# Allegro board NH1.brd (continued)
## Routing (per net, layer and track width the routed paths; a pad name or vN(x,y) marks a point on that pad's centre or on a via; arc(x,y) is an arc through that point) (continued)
PMU_AC_PRESENT: length 3.1
  TOP w0.102: U1.B8 6.15,49.48 5.22,49.48 4.79,49.92 4.13,49.92 R1AS1.2
PMU_BATLOW_N: length 3.6
  TOP w0.102: R1AS2.2 4.46,50.65 4.68,50.42 5.45,50.42 5.7,50.17 6.79,50.17 U1.C9
PMU_PWRBTN_N: length 54.4
  TOP w0.102: v1(2.35,41.69) 2.5,41.53 4.53,41.53 4.72,41.35 4.72,40.24 4.84,40.12 5.44,40.12 5.45,40.14 5.69,40.14 5.73,40.1 6.65,40.1 7.07,39.68 7.07,39.43 7.21,39.3 9.93,39.3 9.97,39.34 10.78,39.34 10.91,39.46 10.91,40.9 11.19,41.18 12.35,41.18 12.41,41.23 12.52,41.23 12.88,41.59 12.88,42.47 13.63,43.21 16.42,43.21 17.22,42.41 17.22,39.72 17.65,39.3 18.41,39.3 18.59,39.12 20.19,39.12 20.41,38.9 20.41,37.86 20.74,37.53 24.22,37.53 24.46,37.78 24.75,37.78 25.79,38.82 28.03,38.82 v1(28.41,39.2) ; v1(5.32,50.98) 5.52,50.81 U1.A10
  IN1 w0.102: v1(5.32,50.98) 5.14,50.81 2.47,50.81 1.76,50.09 1.76,42.27 v1(2.35,41.69)
  BOTTOM w0.102: v1(28.41,39.2) 29.06,39.85 R1P1.1 27.54,40.37 27.11,40.8 CR1P2.3
PMU_SLP_S0IX_N: length 33.6
  TOP w0.102: U1.C7 7.02,48.5 7.02,48.51 6.65,48.51 6.59,48.44 6.04,48.44 5.73,48.13 5.71,48.13 5.55,47.97 5.55,47.51 v1(5.42,47.38) ; TP29.1 10.37,39.1 7.12,39.1 6.87,39.35 6.87,39.6 6.57,39.9 5.66,39.9 v1(5.55,39.78) ; U1AP1.56 17.56,33.33 v1(16.93,32.69)
  IN1 w0.102: v1(5.55,39.78) 5.6,39.78 6.41,40.6 6.41,45.88 5.75,46.54 5.75,47.05 v1(5.42,47.38)
  IN2 w0.102: v1(5.55,39.78) 5.55,39.78 5.55,38.54 7.81,36.28 8.06,36.28 9.43,34.9 15.4,34.9 16.93,33.38 v1(16.93,32.69)
PMU_SLP_S3_N: length 117.6
  TOP w0.102: U1.C8 6.88,49.16 6.6,48.88 6.19,48.88 5.68,48.37 4.84,48.37 v1(4.51,48.04)
  IN2 w0.102: v1(4.51,48.04) 4.51,48.95 3.85,49.61 3.85,55.73 3.36,56.22 3.36,57.84 4.47,58.95 4.47,61.93 4.48,61.95 4.48,61.96 4.48,66.69 2.93,68.23 2.93,73.39 2.58,73.74 2.58,74.05 2.89,74.36 3.13,74.36 3.69,74.92 3.69,78.52 3.96,78.78 4.29,78.78 5.27,79.76 5.27,83.07 7.12,84.92 8.67,84.92 11.2,87.44 12.39,87.44 v1(12.79,87.84)
  BOTTOM w0.102: v1(12.79,87.84) 12.96,87.66 13.99,87.66 14.01,87.69 14.31,87.69 14.33,87.66 15.4,87.66 15.41,87.65 15.51,87.65 16.1,87.06 21.04,87.06 21.51,87.53 24.93,87.53 25.49,88.09 25.78,88.09 26.17,88.47 30.56,88.47 32.17,86.86 32.17,85.32 31.61,84.76 31.61,84.34 30.74,83.48 30.74,82.72 30.08,82.06 30.08,80.48 29.47,79.87 29.47,74.71 29.27,74.5 29.27,73.39 29.5,73.16 29.78,73.16 30.06,72.88 30.06,72.36 29.68,71.98 29.68,71.97 29.67,71.96 29.67,67.97 29.7,67.94 29.93,67.71 30.15,67.5 30.15,64.6 29.63,64.08 29.63,61.31 31.15,59.79 31.15,59.26 31.15,52.2 29.22,50.27 27.59,50.27 27.04,49.71 Q1HDMI3.2
PWRON: length 31
  TOP w0.102: U1AP1.62 v1(15.75,33.74)
  IN1 w0.102: v2(28.71,37.22) 27.09,38.84 26.38,38.84 26.22,38.99 21.45,38.99 19.92,37.47 16.16,37.47 15.56,36.86 15.56,33.94 v1(15.75,33.74)
  IN2 w0.102: v2(28.71,37.22) 29.22,37.72 29.22,40.14 27.85,41.51 v1(27.85,43.52)
  BOTTOM w0.203: v1(27.85,43.52) 28.43,42.93 CR1P2.2 29.24,42.93 C1P3.1 30.74,44.44 30.74,45.39 R1P2.2
REXT_ALS: length 2.2
  TOP w0.102: v1(25.82,90.53) 26.41,89.93 EU1HDMI1.16
  BOTTOM w0.102: R1HDMI2.2 26.21,90.14 v1(25.82,90.53)
RSMRST_N: length 17.4
  TOP w0.102: U1AP1.75 10.55,35.29 v1(10.2,35.64) ; U1.F3 9.12,45.82 v1(9.41,45.53)
  IN1 w0.102: v1(9.41,45.53) 9.14,45.27 9.14,44.34 9.34,44.15 9.74,43.74 10.33,43.74 10.7,43.37 10.7,38.87 10.27,38.44 10.27,35.72 v1(10.2,35.64)
  BOTTOM w0.102: R1AP3.1 9.78,31.59 10.02,31.83 10.02,33.41 9.99,33.44 9.99,35.44 v1(10.2,35.64)
RTEST_N: length 7
  TOP w0.102: C1AS5.1 R1AS5.2 4.43,43.61 4.43,43.75 5.56,44.88 5.97,44.88 5.98,44.89 5.98,44.89 6.16,45.06 6.16,45.35 6.38,45.57 8.17,45.57 U1.E3
RTL8723BS_EN: length 47
  TOP w0.102: R1WF10.1 3.87,19.86 3.87,17.14 4.07,16.94 4.07,16.14 4.63,15.58 v1(4.63,15.58) ; U1.C5 7.43,47.47 v1(7.43,48.82)
  IN1 w0.102: v1(4.63,15.58) 4.98,15.92 4.98,17.14 6.11,18.27 6.11,23.52 5.14,24.49 5.14,24.61 5.14,25.94 5.5,26.3 5.5,27.82 7.2,29.52 7.2,32.8 7.78,33.39 7.78,34.39 6.64,35.53 6.64,36.63 5.03,38.24 5.03,41.2 3.69,42.54 3.69,47.69 4.37,48.37 4.9,48.37 5.05,48.21 5.89,48.21 6.49,48.82 v1(7.43,48.82)
RTL8723BS_EN_R: length 15.6
  TOP w0.102: R65.1 3.23,21.28 R1WF10.2 3.12,20.49 2.88,20.49 R1WF1.2 2.89,19.83 3.2,19.83 3.67,19.36 3.67,17.35 3.31,16.99 3.31,16.39 3.62,16.08 v1(3.72,16.08)
  IN1 w0.102: v2(4.18,10.22) 4.18,15.02 3.72,15.48 v1(3.72,16.08)
  BOTTOM w0.102: U1WF1.13 3.43,9.44 4.18,10.19 v2(4.18,10.22)
SDMMC1_RCOMP: length 3.7
  TOP w0.254: R1AS43.1 23.89,46.77 22.81,47.85 U1.AE6
SDMMC2_CLK: length 46.9
  TOP w0.102: v1(22,50.18) 22,50.15 U1.AE9
  IN2 w0.102: v1(13.21,19.28) 13.22,19.28 13.42,19.49 13.42,20.91 13.4,20.93 13.83,21.37 15.96,21.37 16.42,21.82 16.82,21.82 17.97,22.97 19.16,22.97 19.33,23.14 23.25,23.14 24.24,24.14 24.24,31.8 23.88,32.16 23.88,34.85 23.07,35.66 23.07,49.09 22.65,49.52 22.65,49.52 v1(22,50.18)
  BOTTOM w0.14: C1WF21.2 13.55,23.06 13.62,22.99 U1WF1.33 13.62,20.71 13.21,20.3 v1(13.21,19.28)
SDMMC2_CMD: length 48
  TOP w0.102: U1.AC9 v1(20.71,49.48)
  IN2 w0.102: v1(20.71,49.48) 21.04,49.81 21.48,49.81 21.49,49.8 21.51,49.8 22.72,48.6 22.72,35.51 23.53,34.7 23.53,32.01 23.89,31.65 23.89,24.29 23.1,23.5 19.19,23.5 19.01,23.32 17.82,23.32 16.68,22.18 16.27,22.18 15.81,21.72 13.68,21.72 12.96,21.01 12.96,20.02 12.61,19.66 8.47,19.66 v1(7.96,20.17)
  BOTTOM w0.14: v1(7.96,20.17) 8.37,20.58 U1WF1.28
SDMMC2_D_0: length 52.9
  TOP w0.102: U1.AB11 19.4,50.83 v1(19.4,50.83)
  IN2 w0.102: v1(19.4,50.83) 19.95,51.38 22.63,51.38 24.52,49.49 24.52,36.01 25.15,35.37 25.15,32.69 25.51,32.33 25.51,23.61 23.09,21.19 21.11,21.19 20.6,21.7 18.52,21.7 14.58,17.76 v1(12.16,17.76)
  BOTTOM w0.14: v1(12.16,17.76) 12.16,20.45 12.57,20.86 U1WF1.32
SDMMC2_D_1: length 52.3
  TOP w0.102: U1.AB10 19.4,50.18 v1(19.4,50.18)
  IN2 w0.102: v1(19.4,50.18) 20.35,51.13 22.45,51.13 24.17,49.42 24.17,35.93 24.85,35.25 24.85,32.56 25.21,32.2 25.21,23.74 23.65,22.18 19.77,22.18 19.59,22 18.37,22 17.22,20.86 17.2,20.86 14.63,18.29 14.62,18.29 14.46,18.14 v1(11.11,18.14)
  BOTTOM w0.14: U1WF1.31 11.52,20.3 11.11,19.89 v1(11.11,18.14)
SDMMC2_D_2: length 50.6
  TOP w0.102: U1.AC10 v1(20.7,50.18)
  IN2 w0.102: v1(20.7,50.18) 21.24,50.72 21.25,50.72 21.4,50.88 22.25,50.88 23.84,49.29 23.84,35.83 24.54,35.12 24.54,32.43 24.9,32.07 24.9,23.87 23.52,22.48 19.61,22.48 19.43,22.31 18.24,22.31 17.1,21.16 17.07,21.16 14.51,18.6 14.49,18.6 14.41,18.52 v1(10.06,18.52)
  BOTTOM w0.14: v1(10.06,18.52) 10.06,20.15 10.47,20.55 U1WF1.30
SDMMC2_D_3: length 49.4
  TOP w0.102: U1.AD10 v1(21.35,50.18)
  IN2 w0.102: v1(21.35,50.18) 21.35,50.22 21.68,50.55 22.12,50.55 23.43,49.24 23.43,35.8 24.24,34.99 24.24,32.31 24.6,31.95 24.6,23.99 23.39,22.79 19.48,22.79 19.3,22.61 18.11,22.61 16.97,21.47 16.94,21.47 14.38,18.9 v1(9.01,18.9)
  BOTTOM w0.14: U1WF1.29 9.42,19.31 v1(9.01,18.9)
SDMMC3_CD_N: length 58.4
  TOP w0.102: v1(18.07,51.47) U1.Y12 ; J1SD1.9 12.65,12.26 v1(12.61,12.3)
  IN2 w0.102: v1(12.61,20.17) 12.58,20.2 12.58,21.14 13.65,22.2 15.71,22.2 v1(16.09,22.59) 16.09,22.61 17.11,23.63 18.88,23.63 19.06,23.8 22.97,23.8 23.58,24.41 23.58,31.53 23.22,31.88 23.22,34.57 22.36,35.43 22.36,39.86 21.8,40.42 21.8,41.43 21.8,41.43 21.8,46.23 20.19,47.84 18.57,47.84 18.37,48.04 18.37,48.92 18.43,48.98 18.43,50.02 18.07,50.38 v1(18.07,51.47)
  BOTTOM w0.102: v1(18.07,51.47) 18.4,51.8 18.92,51.8 19.16,51.56 19.24,51.56 19.66,51.14 19.76,51.14 R60.2 ; v1(12.61,12.3) 12.71,12.4 12.71,20.07 v1(12.61,20.17)
  BOTTOM w0.254: v1(16.09,22.59) 16.09,22.98 16.95,23.85 C73.1
SDMMC3_CLK: length 52.2
  TOP w0.102: U1.AC12 20.55,51.81 20.86,51.49 22.52,51.49 22.62,51.39 22.77,51.39
  TOP w0.14: v1(25.87,39.4) 26.43,39.96 26.43,41.64 26.8,42.01 26.8,48.48 25.26,50.02 24.74,50.02 23.38,51.39 22.77,51.39 ; U15.6 v1(17.92,12.26)
  IN1 w0.102: v1(22.97,19.92) 21.24,18.24 18.96,18.24 16.57,15.85 16.57,13.36 17.66,12.27 17.91,12.27 v1(17.92,12.26)
  BOTTOM w0.14: v1(25.87,39.4) 25.87,39 27.23,37.63 27.23,33.13 24.42,30.32 24.42,21.9 22.97,20.45 v1(22.97,19.92)
SDMMC3_CLK_CONN: length 8.1
  TOP w0.14: U15.11 15.31,12.26 15.17,12.4 v2(15.02,12.4)
  BOTTOM w0.14: v2(15.02,12.4) 15.02,10.52 15.5,10.04 17.1,10.04 17.46,9.68 17.46,9.07 18.29,8.24 R66.1
SDMMC3_CLK_CONN_R: length 23.5
  TOP w0.14: J1SD1.5 2.25,14.14 2.26,14.15 3.15,14.15 3.21,14.2 4.07,14.2 5.24,13.03 13.02,13.03 v2(13.27,12.78)
  BOTTOM w0.102: v2(13.27,12.78) 14.74,11.31 14.74,9.51 15.4,8.84 16.85,8.84 18.32,7.37 18.32,6.41 18.53,6.21 C418.2 R66.2
SDMMC3_CMD: length 53.8
  TOP w0.102: 22.77,51.03 22.62,51.03 22.41,51.24 20.71,51.24 20.47,51.48 20.05,51.48 U1.AB12
  TOP w0.14: 22.77,51.03 23.26,51.03 24.58,49.72 25.13,49.72 26.5,48.35 26.5,42.14 26.12,41.76 26.12,40.39 v1(25.49,39.76) ; U15.5 v1(18.32,11.86)
  IN1 w0.102: v1(22.41,19.92) 20.99,18.55 18.83,18.55 16.27,15.98 16.27,13.24 17.64,11.87 18.32,11.87 v1(18.32,11.86)
  BOTTOM w0.14: v1(25.49,39.76) 25.49,38.95 26.91,37.52 26.91,33.24 24.11,30.45 24.11,22.03 22.41,20.32 v1(22.41,19.92)
SDMMC3_CMD_CONN: length 14.8
  TOP w0.14: U15.12 14.89,11.86 14.57,11.54 13.64,11.54 13.25,11.92 12.45,11.92 12.44,11.94 J1SD1.3
SDMMC3_D_0: length 52.2
  TOP w0.102: U1.AC11 20.54,50.98 22.23,50.98 22.54,50.68 22.77,50.68
  TOP w0.14: U15.7 v1(18.27,12.66) ; v1(25.26,40.26) 25.73,40.74 25.73,42.06 26.19,42.52 26.19,48.23 25,49.41 24.7,49.41 24.7,49.41 24.45,49.41 23.19,50.68 22.77,50.68
  IN1 w0.102: v1(18.27,12.66) 18.26,12.68 17.69,12.68 16.88,13.49 16.88,15.7 19.11,17.94 21.5,17.94 v1(23.53,19.92)
  BOTTOM w0.14: v1(23.53,19.92) 23.53,20.5 24.72,21.7 24.72,30.19 27.65,33.11 27.65,37.65 26.28,39.02 26.28,39.85 25.87,40.26 v1(25.26,40.26)
SDMMC3_D_1: length 52.9
  TOP w0.102: 22.6,51.74 22.21,51.74 21.87,52.09 21.61,52.09 21.35,52.35 21.35,52.56 21.15,52.76 20,52.76 U1.AB13
  TOP w0.14: U15.8 v1(17.89,13.06) ; 22.6,51.74 22.62,51.73 23.47,51.73 24.87,50.33 25.38,50.33 27.11,48.61 27.11,41.88 26.73,41.51 26.73,40.35 26.99,40.1 26.99,39.5 v1(26.65,39.17)
  IN1 w0.102: v1(24.09,19.92) 21.75,17.63 19.24,17.63 17.18,15.58 17.18,13.62 17.71,13.09 17.87,13.09 v1(17.89,13.06)
  BOTTOM w0.14: v1(26.65,39.17) 27.95,37.88 27.95,32.99 25.03,30.07 25.03,21.54 24.09,20.6 v1(24.09,19.92)
SDMMC3_D_2: length 56
  TOP w0.102: U1.AA12 v1(19.4,52.13)
  TOP w0.14: v1(18.04,10.65) 17.63,11.06 U15.3
  IN1 w0.102: v1(21.85,19.92) 20.74,18.85 18.71,18.85 15.96,16.11 15.96,12.98 17.41,11.54 18.23,11.54 18.24,11.53 18.28,11.53 18.45,11.36 18.45,11.05 v1(18.04,10.65)
  BOTTOM w0.14: v1(21.85,19.92) 21.85,20.2 23.81,22.15 23.81,30.57 26.6,33.37 26.6,37.34 24.88,39.06 24.88,40.5 25.13,40.75 25.95,40.75 26.43,41.23 26.43,43 24.48,44.95 24.48,48.71 21.55,51.64 19.87,51.64 19.66,51.85 19.66,51.86 v1(19.4,52.13)
SDMMC3_D_3: length 55.7
  TOP w0.102: U1.AA13 v1(18.75,52.13)
  TOP w0.14: v1(18.09,11.21) 17.84,11.46 U15.4
  IN1 w0.102: v1(21.3,19.92) 20.48,19.16 18.58,19.16 15.66,16.23 15.66,12.73 17.18,11.21 v1(18.09,11.21)
  BOTTOM w0.14: v1(18.75,52.13) 18.9,52.13 19.25,51.78 19.33,51.78 19.75,51.36 21.49,51.36 22.46,50.39 22.46,50.3 24.18,48.58 24.18,44.82 26.13,42.87 26.13,41.35 25.83,41.05 24.88,41.05 24.5,40.67 24.5,38.99 26.3,37.19 26.3,33.49 23.51,30.7 23.51,22.29 21.3,20.08 v1(21.3,19.92)
SDMMC3_DATA0_CONN: length 16
  TOP w0.14: U15.10 15.53,12.66 14.8,13.39 5.6,13.39 3.59,15.4 3.43,15.4 2.5,16.34 J1SD1.7
SDMMC3_DATA1_CONN: length 16.6
  TOP w0.14: U15.9 15.68,13.06 15.05,13.7 5.75,13.7 3.74,15.71 3.56,15.71 3.03,16.24 3.03,16.76 2.35,17.44 J1SD1.8
SDMMC3_DATA2_CONN: length 15.4
  TOP w0.14: J1SD1.1 2.3,9.74 3.88,11.31 13,11.31 13.38,10.93 14.82,10.93 14.95,11.06 U15.14
SDMMC3_DATA3_CONN: length 15.1
  TOP w0.14: U15.13 14.92,11.46 14.69,11.24 13.51,11.24 13.13,11.62 3.29,11.62 2.51,10.84 J1SD1.2
SDMMC3_RCOMP: length 3.8
  TOP w0.254: U1.AE10 21.76,50.58 22.24,50.58 22.55,50.27 23.08,50.27 24.3,49.05 24.31,49.05 24.43,48.93 R1AS44.1
SLP_S3_3P3_N: length 52.5
  IN2 w0.102: v2(30.85,47.48) 31.2,47.83 31.2,62.26 v2(31.15,62.31)
  BOTTOM w0.102: Q1HDMI3.3 29.07,45.8 30.74,47.48 v2(30.85,47.48) ; R1HDMI1.1 28.38,89.12 28.4,89.11 28.69,89.11 29.22,89.64 R1HDMI8.1 29.3,90.02 32.37,86.95 32.37,85.23 31.81,84.67 31.81,84.26 30.95,83.39 30.95,82.63 30.29,81.97 30.29,80.4 29.68,79.79 29.68,74.9 30.95,73.63 30.95,69.88 30.08,69.01 30.08,68.14 30.55,67.66 30.74,67.47 30.74,64.55 30.08,63.89 30.08,63.86 30.08,63.86 30.08,63.14 30.08,63.13 30.08,63.02 30.8,62.31 v2(31.15,62.31)
SOC_PMIC_INT: length 29.8
  TOP w0.102: v1(8.14,50.17) 8.43,49.88 U1.E9 ; U1AP1.64 14.95,35.17 v1(14.64,35.48)
  IN1 w0.102: v1(6.51,39.45) 6.26,39.2 5.66,39.2 5.21,39.65 5.21,41.28 3.9,42.59 3.9,46.74 5.11,47.96 5.99,47.96 6.52,48.49 7.61,48.49 8.14,49.03 v1(8.14,50.17)
  IN2 w0.102: v1(6.51,39.45) 7.25,39.45 7.68,39.02 7.68,37.17 8.14,36.71 13.42,36.71 v1(14.64,35.48)
  BOTTOM w0.102: TP26.1 8.36,50.93 R2AS4.1 8.31,50.17 v1(8.14,50.17)
SPI_NOR_CLK: length 37.6
  TOP w0.102: v1(27.59,60.69) 27.85,60.94 27.85,60.95 28.99,62.08 30.07,62.08 30.73,61.42 30.73,57.4 30.03,56.71 30.03,53.39 31.11,52.31 EU1SPI1.6 ; v1(9.41,52.13) U1.F12
  IN1 w0.102: v1(9.41,52.13) 10.42,53.15 10.42,53.75 11.14,54.47 15.02,54.47 15.15,54.34 15.68,54.34 16.04,54.69 17.28,54.69 17.71,55.12 19.21,55.12 20.46,56.37 21.56,56.37 25.55,60.36 27.26,60.36 v1(27.59,60.69)
SPI_NOR_CS0_N: length 51.7
  TOP w0.102: R1SPI1.1 28.57,41.46 EU1SPI1.1 28.57,44.88 27.65,45.8 27.65,48.75 26.74,49.67 26.74,51.02 26.82,51.1 27.11,51.1 27.72,51.72 27.72,52.02 28.56,52.86 29.17,52.86 29.83,53.52 29.83,56.79 30.53,57.49 30.53,61.32 30.07,61.78 29.36,61.78 27.91,60.33 27.45,60.33 26.87,60.91 v1(26.87,60.94) ; U1.C12 7.13,51.81 v1(7.46,52.13)
  IN1 w0.102: v1(26.87,60.94) 26.74,60.81 25.17,60.81 21.24,56.88 21.12,56.88 21.12,56.88 19.34,56.88 18.53,56.06 16.5,56.06 16.22,55.79 13.73,55.79 13.73,55.78 11.58,55.78 9.6,53.8 9.32,53.8 9.13,53.61 9.13,53.33 8.53,52.74 8.06,52.74 v1(7.46,52.13)
SPI_NOR_MISO: length 42.1
  TOP w0.102: R1SPI3.2 29.98,40.79 29.98,41.38 v2(30.29,41.69) ; v1(8.75,52.15) 8.43,52.47 U1.E13
  IN1 w0.102: v1(8.75,52.15) 9.1,51.8 9.26,51.8 9.27,51.8 9.61,51.8 10.24,52.43 11.29,52.43 11.29,52.43 12.3,52.43 13.67,53.8 16.87,53.8 17.31,54.23 20.05,54.23 21.8,55.99 21.8,56.15 22.06,56.4 22.95,56.4 24.21,57.66 24.21,58.02 24.84,58.65 26.82,58.65 27.9,57.57 27.9,57.18 v1(28.64,56.44)
  IN2 w0.102: v2(30.29,41.69) 29.88,42.09 29.88,54.74 28.64,55.99 v1(28.64,56.44)
SPI_NOR_MISO_R: length 2.8
  TOP w0.102: R1SPI3.1 29.37,41.52 29.84,41.99 EU1SPI1.2
SPI_NOR_MOSI: length 40.1
  TOP w0.102: v1(27.59,61.19) 28.69,62.29 30.15,62.29 30.93,61.51 30.93,57.32 30.24,56.62 30.24,53.61 31.6,52.25 32.27,52.25 32.38,52.14 EU1SPI1.5 ; v1(8.11,52.13) U1.E12
  IN1 w0.102: v1(8.11,52.13) 8.46,52.48 8.64,52.48 9.27,53.12 9.29,53.12 9.3,53.12 9.82,53.12 10.15,53.46 10.15,54 11.29,55.13 15.92,55.13 16.6,55.81 16.89,55.81 16.9,55.79 19.52,55.79 20.36,56.62 21.41,56.62 25.34,60.56 27.03,60.56 27.25,60.78 27.25,60.85 v1(27.59,61.19)
SRTCRST_N: length 6.5
  TOP w0.102: U1.E4 8.13,46.19 5.69,46.19 5.5,45.99 5.5,45.65 5.3,45.45 4.11,45.45 C1AS4.1 R1AS11.2
SUS_CLK_WLAN: length 40.1
  TOP w0.102: v1(5.38,49.81) 5.82,49.81 U1.A9 ; v1(4.23,17.3) 4.07,17.45 4.07,19.94 4.02,19.99 4.02,20.38 R1WF11.1
  IN1 w0.102: v1(4.23,17.3) 3.62,17.3 2.93,17.99 2.93,21.91 3.13,22.11 3.13,23.42 2.93,23.62 2.93,28.46 4.23,29.76 4.23,38.74 3.16,39.81 3.16,48.03 4.95,49.81 v1(5.38,49.81)
SUSPWRDNACK: length 24.8
  TOP w0.102: v1(6.81,50.83) 7.46,50.83 U1.D10
  IN1 w0.102: v1(6.81,50.83) 6.81,50.44 6.06,49.69 6.06,49.1 5.67,48.72 5.26,48.72 5.11,48.87 4.37,48.87 3.34,47.84 3.34,41.05 v1(4.48,39.91)
  IN2 w0.102: v1(4.48,39.91) 4.79,40.21 7.02,40.21 7.88,39.35 7.88,37.37 8.29,36.96 10.53,36.96 v1(10.73,37.17)
  BOTTOM w0.102: R63.1 10.71,37.18 v1(10.73,37.17)
SUSPWRDNACK_R: length 10.3
  TOP w0.102: U1AP1.63 15.35,36.06 15.66,36.36 v1(15.66,38.08)
  BOTTOM w0.102: R63.2 10.2,38.34 R64.2 11.91,39.04 14.69,39.04 v1(15.66,38.08)
TP_CFG_ALS: length 3.1
  TOP w0.102: EU1HDMI1.20 25.07,87.01 v1(25,86.95)
  BOTTOM w0.102: v1(25,86.95) 24.66,87.3 23.92,87.3 23.38,86.76 TP17.1
TP_DDI0_HDMI_CEC: length 4.6
  TOP w0.102: J1HDMI1.13 15.25,88.55 15.66,88.14 15.66,87.15 15.96,86.85 TP12.1
TP_DDI0_HDMI_UTILITY: length 4.7
  TOP w0.102: TP13.1 14.74,87.23 15.17,87.66 v1(15.17,88.04)
  BOTTOM w0.102: J1HDMI1.14 14.75,88.46 v1(15.17,88.04)
TP_EQ_ALS: length 3
  TOP w0.117: TP16.1 29.25,90.69 28.75,90.69 28.74,90.68 28.71,90.68 27.61,89.58 EU1HDMI1.13
TP_LED_BT: length 7.5
  TOP w0.102: TP18.1 12.83,7.22 v1(10.47,9.58)
  BOTTOM w0.102: U1WF1.5 v1(10.47,9.58)
TP_LED_WLAN: length 9.6
  TOP w0.102: TP19.1 15.4,6.43 14.89,6.94 12.51,6.94 9.87,9.58 v1(9.42,9.58)
  BOTTOM w0.254: U1WF1.6 v1(9.42,9.58)
TP_PRE_ALS: length 1.2
  TOP w0.102: TP14.1 26.81,90.3 EU1HDMI1.15
TP_WIFI_CLK_REQ: length 9.7
  BOTTOM w0.102: TP20.1 5.04,27.61 5.04,24.29 5.14,24.19 6.38,24.19 6.61,23.95 6.61,23.14 6.46,22.99 5.6,22.99 5.22,22.61 U1WF1.25
UART3_RXD: length 3.2
  TOP w0.102: U1.AD6 21.02,47.89 21.37,48.24 23.53,48.24 TP22.1
UART3_TXD: length 7.4
  TOP w0.102: TP21.1 23.31,44.11 23.31,45.09 22.58,45.81 22.2,45.81 21.8,46.21 21.52,46.21 21.3,46.43 21.3,46.62 21.14,46.79 20.84,46.79 20.69,46.94 20.69,47.54 U1.AC6
UART_1_BT_CTS: length 79.3
  TOP w0.102: U1.AB18 19.73,55.8 v1(20.05,55.48)
  IN2 w0.102: v1(7.91,14.08) 15.32,14.08 19.18,17.94 19.3,17.94 21.12,17.94 21.52,18.34 25.4,18.34 30.08,23.03 30.08,23.98 30.24,24.13 30.24,40.98 29.6,41.61 29.6,54.72 28.75,55.58 28.74,55.58 28.45,55.58 28.45,55.58 26.95,55.58 25.63,56.9 24.38,56.9 23.27,58.01 22.64,58.01 20.1,55.48 v1(20.05,55.48)
  BOTTOM w0.102: U1WF1.24 4.17,21.12 7.91,17.38 v1(7.91,14.08)
UART_1_BT_RTS: length 75.1
  TOP w0.102: U1.AC18 20.38,55.8 v1(20.7,55.48)
  IN2 w0.102: v1(20.7,55.48) 20.7,55.62 21.88,56.8 21.88,56.8 22.66,57.58 22.66,57.58 22.71,57.63 23.29,57.63 24.28,56.65 25.45,56.65 29.4,52.69 29.4,41.48 30.03,40.85 30.03,24.21 29.88,24.06 29.88,23.11 25.31,18.55 21.37,18.55 20.97,18.14 19.21,18.14 19.09,18.14 15.41,14.46 v1(8.29,14.46)
  BOTTOM w0.102: v1(8.29,14.46) 8.29,17.38 6.27,19.4 U1WF1.26
UART_1_BT_RXD: length 74
  TOP w0.102: U1.AB19 20.04,56.14 22.01,56.14 v1(22.13,56.01)
  IN2 w0.102: v1(8.67,14.81) 15.48,14.81 19.01,18.34 19.13,18.34 20.88,18.34 21.29,18.75 25.23,18.75 29.68,23.2 29.68,24.14 29.83,24.3 29.83,40.67 29.15,41.35 29.15,52.64 25.4,56.39 24.07,56.39 23.09,57.38 22.82,57.38 22.13,56.7 v1(22.13,56.01)
  BOTTOM w0.102: U1WF1.27 7.32,18.86 8.67,17.51 v1(8.67,14.81)
UART_1_BT_TXD: length 71.4
  TOP w0.102: v1(22.84,55.83) 22.84,55.89 22.31,56.42 20.41,56.42 U1.AC19
  IN2 w0.102: v1(22.84,55.83) 23.35,55.83 25.45,53.73 26.81,53.73 28.46,52.08 28.46,46.91 27.34,45.79 27.34,41.73 28.99,40.08 28.99,38.08 28.26,37.34 28.26,22.06 25.15,18.95 21.2,18.95 20.8,18.55 19.04,18.55 18.93,18.55 15.6,15.22 4.32,15.22 3.82,15.72 3.57,15.72 3.36,15.93 3.36,16.29 v1(3.72,16.64)
  BOTTOM w0.102: v1(3.72,16.64) 3.53,16.46 U1WF1.19
UART_RTS_8723: length 6.9
  TOP w0.102: R1WF11.2 4.28,19.86 4.28,17.76 4.37,17.67 4.37,17.66 4.58,17.45 4.58,17.09 4.28,16.79 4.28,16.44 v1(4.63,16.08)
  BOTTOM w0.102: v1(4.63,16.08) 3.84,15.29 U1WF1.18
USB2_P0_CMC_DN: length 16.3
  TOP w0.131: v1(19.24,13.01) 19.07,13.17 19.07,13.48 18.12,14.44 16.69,14.44 16.41,14.72 16.41,15.05 16.54,15.18 CR1USB2.2
  BOTTOM w0.131: J1USB3.3 20.46,10.34 20.18,10.06 19.2,10.06 19.11,10.15 19.11,12.89 v1(19.24,13.01) 19.1,13.15 19.1,13.96 18.46,14.6 18.46,16.8 19.47,17.81 19.47,17.96 19.65,18.15 L1USB1.1 19.65,18.51 R1USB1.2
USB2_P0_CMC_DP: length 16.3
  TOP w0.131: CR1USB1.2 16.04,15.18 16.18,15.05 16.18,14.62 16.59,14.2 18.02,14.2 18.84,13.38 18.84,13.15 v1(18.7,13.01)
  BOTTOM w0.131: J1USB3.2 19.63,9.83 19.1,9.83 18.88,10.05 18.88,12.83 v1(18.7,13.01) 18.87,13.17 18.87,13.86 18.22,14.51 18.22,16.7 18.22,16.9 19.23,17.91 19.23,18.03 19.1,18.17 L1USB1.4 19.1,18.51 R1USB2.2
USB2_P0_DN: length 53.4
  TOP w0.089: U1.G3 9.78,45.86 v1(10.1,46.17)
  IN1 w0.117: v1(19.92,21.26) 19.87,21.32 19.65,21.32 19.53,21.2 19.53,20.87 19.63,20.77 28.07,20.77 29.38,22.09 29.38,37.31 25.96,40.73 16,40.73 12.24,44.49 12.24,45.46 11.15,46.55 10.31,46.55 10.1,46.34 v1(10.1,46.17)
  BOTTOM w0.131: v1(19.92,21.26) 19.77,21.42 19.62,21.42 19.51,21.3 19.51,21.11 19.42,21.02 19.42,20.47 19.65,20.24 L1USB1.2 19.65,19.75 R1USB1.1
USB2_P0_DP: length 53.5
  TOP w0.089: v1(10.1,46.82) 9.79,46.51 U1.G4
  IN1 w0.117: v1(10.1,46.82) 11.26,46.82 12.51,45.57 12.51,44.61 16.11,41 26.07,41 29.65,37.42 29.65,21.98 28.18,20.5 19.52,20.5 19.26,20.76 19.26,21.14 v1(19.14,21.26)
  BOTTOM w0.131: v1(19.14,21.26) 19.19,21.21 19.19,20.33 19.09,20.24 19.09,19.76 L1USB1.3 19.1,19.75 R1USB2.1
USB2_P1_CMC_DN: length 5.3
  TOP w0.131: J1USB2.2 6.19,34.65 v2(6.67,34.17)
  BOTTOM w0.131: R2USB1.2 6.64,36.52 L1USB2.1 6.64,35.93 6.54,35.83 6.54,35.52 CR2USB1.2 6.67,34.67 v2(6.67,34.17)
USB2_P1_CMC_DP: length 5.2
  TOP w0.131: v2(6,34.17) 6,34.29 5.88,34.42 5.52,34.42 5.1,34 J1USB2.3
  BOTTOM w0.131: R2USB2.2 6.09,36.52 L1USB2.4 6.09,36.12 6.31,35.9 6.31,35.54 5.79,35.03 CR2USB2.2 6.24,34.48 6.24,34.3 6.12,34.17 v2(6,34.17)
USB2_P1_DN: length 27.7
  TOP w0.089: U1.H3 10.1,45.53 v1(10.1,45.52)
  IN1 w0.102: 12.01,43.29 12,43.3 12,43.31 11.94,43.37 11.94,43.37 11.54,43.77 11.54,44.78 10.47,45.85 10.23,45.85 10.1,45.73 v1(10.1,45.52)
  IN1 w0.117: v2(6.77,38.71) 6.69,38.79 6.55,38.79 6.38,38.62 6.38,37.99 7.4,36.96 7.4,35.84 8.56,34.68 8.56,33.71 9.27,33 12.81,33 13.1,33.29 13.1,39.24 13.17,39.31 13.17,42.13 12.01,43.29
  BOTTOM w0.131: R2USB1.1 6.64,37.76 L1USB2.2 6.64,38.19 6.44,38.38 6.44,38.58 6.57,38.71 v2(6.77,38.71)
USB2_P1_DP: length 27.8
  TOP w0.089: U1.H4 10.75,46.19 v1(10.75,46.17)
  IN1 w0.102: 12.2,43.48 12.19,43.49 12.18,43.49 11.8,43.87 11.8,44.88 10.75,45.93 v1(10.75,46.17)
  IN1 w0.117: 12.2,43.48 13.44,42.24 13.44,39.2 13.37,39.13 13.37,33.18 12.92,32.73 9.16,32.73 8.29,33.6 8.29,34.57 7.13,35.73 7.13,36.85 6.11,37.88 6.11,38.56 v2(5.95,38.71)
  BOTTOM w0.131: R2USB2.1 6.09,37.76 L1USB2.3 6.09,38.16 6.21,38.28 6.21,38.46 v2(5.95,38.71)
USB_OC#: length 83.6
  TOP w0.102: v1(7.46,54.13) 7.46,53.73 7.67,53.52 7.8,53.52 8.06,53.26 8.06,53.09 8.39,52.76 8.8,52.76 U1.F13 ; U28.5 31.2,20.72 C414.2 31.53,19.91 31.41,19.79 R1WF14.1 30.99,18.84 29.61,18.84 v2(29.32,18.55)
  IN1 w0.102: v1(3.82,13.8) 2.58,15.04 2.58,22.05 2.78,22.26 2.78,23.27 2.58,23.47 2.58,28.61 3.85,29.88 3.85,38.56 2.63,39.78 2.63,40.65 1.33,41.94 1.33,50.68 2.64,51.99 5.04,51.99 5.45,52.4 5.45,53.89 6.02,54.46 7.13,54.46 v1(7.46,54.13)
  IN2 w0.102: v1(3.82,13.8) 3.92,13.7 15.23,13.7 19.26,17.73 21.2,17.73 21.59,18.12 22.93,18.12 23.05,18.12 28.89,18.12 v2(29.32,18.55)
USB_RCOMP: length 3.4
  TOP w0.254: R1AS46.2 11.47,43.05 11.11,43.41 10.77,43.41 10.36,43.82 9.86,43.82 U1.F1
USB_ULPI_0_CS: length 4.1
  TOP w0.254: R1AS4.1 24.22,45.02 22.07,47.18 U1.AE5
V_1P8_VINT: length 3.4
  TOP w0.203: U1AP1.54 19.11,32.53 C1AP38.1
  TOP w0.254: C1AP38.1 R1AP4.1
V_PMIC_VREF: length 5
  TOP w0.203: 17.91,24.99 17.66,24.99 17.35,25.29 U1AP1.38
  TOP w0.254: 17.91,24.99 18.27,24.99 18.64,24.62 18.65,24.62 18.96,24.31 18.96,24.3 19.23,24.04 19.23,23.97 19.23,23.46 19.54,23.14 20.07,23.14 C1AP40.1
V_USB:
  vias: v1(28.41,20.05) v1(28.44,19.54) v1(28.44,19.03) v1(28.61,22.64) v2(4.89,35.95) v2(4.89,19.28) v2(4.89,18.67) v2(4.89,18.01) v2(5.09,36.61) v2(5.5,35.95)
WINDOWS_ANDROID: length 39.2
  TOP w0.102: U1.AC5 20.37,46.9 20.65,46.62 20.65,45.78 20.9,45.54 21.53,45.54 21.54,45.53 21.81,45.53 21.83,45.55 22.3,45.55 22.55,45.3 22.55,43.14 v1(22.31,42.91) ; v1(29.2,65.26) 28.3,64.36 R58.1 R59.2
  IN1 w0.102: v1(22.31,42.91) 22.87,42.35 27.67,42.35 v1(30.26,44.94)
  IN2 w0.102: v1(30.26,44.94) 30.26,54.72 29.2,55.78 v1(29.2,65.26)
WL_DEV_EN: length 4.8
  TOP w0.102: R1WF4.1 3.08,4.72 v2(5.22,6.86)
  BOTTOM w0.102: U1WF1.10 v2(5.22,6.86)
WLAN_HOST_WAKE: length 4.8
  TOP w0.102: v2(4.17,6.89) 4.17,6.32 2.07,4.22 R1WF6.2
  BOTTOM w0.102: U1WF1.11 v2(4.17,6.89)
WP_N_FLASH: length 2.9
  TOP w0.102: R1SPI2.1 31.11,41.68 EU1SPI1.3
XDP_H_TCK: length 1.5
  TOP w0.102: v1(8.8,47.5) 8.48,47.18 U1.E5
  BOTTOM w0.102: R2AS5.2 8.68,47.62 v1(8.8,47.5)
XDP_H_TDI: length 7
  TOP w0.102: v1(8.8,45.53) 8.8,46.19 U1.F4
  BOTTOM w0.102: v1(8.8,45.53) 9.15,45.18 9.15,44.68 9.66,44.18 9.66,43.36 9.66,43.19 10.35,42.51 10.45,42.51 10.66,42.3 10.66,40.79 R2AS7.1
XDP_H_TMS: length 9.9
  TOP w0.102: v1(10.75,47.5) 10.45,47.81 U1.H6
  BOTTOM w0.102: R2AS6.1 10.86,39.98 10.86,42.39 10.53,42.71 10.43,42.71 9.87,43.28 9.87,44.12 10.63,44.89 10.63,45.5 11.34,46.21 11.34,46.92 v1(10.75,47.5)
XDP_H_TRST_N: length 2
  TOP w0.102: U1.G6 9.78,47.86 v1(9.46,48.18)
  BOTTOM w0.102: v1(9.46,48.18) 9.07,48.56 9.07,48.76 8.88,48.95 R2AS8.2
XTAL25_IN: length 6.5
  TOP w0.102: U1.V3 17.07,45.73 17.63,45.17 17.63,40.59 17.85,40.37 17.97,40.37 R1AS52.1
XTAL25_IN_R1: length 4
  TOP w0.102: Y2.1 21.96,40.48 C1AS63.1 21.04,40.24 20.65,40.24 20.26,40.62 R1AS50.2 19.63,40.63 19.51,40.75 R1AS52.2
XTAL25_OUT: length 6.2
  TOP w0.102: R1AS53.1 17.92,40.16 17.77,40.16 17.43,40.5 17.43,45.03 17.25,45.21 U1.V2
XTAL25_OUT_R2: length 6
  TOP w0.102: Y2.3 23.41,39.74 21.8,39.74 21.3,39.23 C1AS64.1 20.66,39.85 R1AS50.1 19.75,39.85 19.63,39.73 R1AS53.2
N01645: length 3.7
  TOP w0.305: v2(11.59,4.68) 10.75,3.83 ANT1001.1
  BOTTOM w0.305: v2(11.59,4.68) 10.95,4.03 C1WF7.2 FB1WF3.1
N16460136: length 4
  TOP w0.102: 13.75,35.41 13.75,35.87 13.98,36.1 14.68,36.1 R1AP5.1 ; 13.75,35.41 13.5,35.41 13.35,35.27 U1AP1.68 ; 13.75,35.41 U1AP1.67
N16460500: length 1.6
  TOP w0.102: v1(16.29,24.74) 16.15,24.88 U1AP1.35
  BOTTOM w0.102: v1(16.29,24.74) 16.18,24.63 R1AP2.2
N16461220: length 7.7
  BOTTOM w0.102: R1AP12.2 3.7,28.88 4.63,28.88 5.01,28.5 5.01,28.05 5.5,27.56 5.5,26.32 5.81,26.01 7.03,26.01 C1AP26.1 8.04,26.52 v1(8.29,26.78)
N16805407: length 24.4
  TOP w0.508: CR1P3.2 6.8,1.89 v2(7.07,2.16) ; v2(11.74,10.12) 11.71,10.15 5.14,10.15 v2(5.05,10.06)
  IN1 w0.508: v2(11.74,10.12) 11.74,6.26 12.62,5.38 v2(12.62,4.39) ; v2(5.05,10.06) 5.05,8.96 7.63,6.38 7.63,2.72 v2(7.07,2.16)
  BOTTOM w0.508: R1P3.1 12.89,4.12 v2(12.62,4.39)
N16805481: length 33.7
  TOP w0.102: SW1P1.1 29.9,77.8 29.9,75.21 29.9,75.21 29.9,74.38 29.98,74.3 29.98,73.89 v1(29.63,73.59)
  BOTTOM w0.102: v1(29.63,73.59) 29.93,73.59 30.26,73.26 30.26,72.27 29.88,71.89 29.88,70.35 29.88,70.34 29.88,68.05 30.35,67.58 30.54,67.39 30.54,64.63 29.83,63.92 29.83,61.4 31.35,59.87 31.35,47.29 30.82,46.75 30.82,46.75 R1P2.1
N16806211: length 20.3
  TOP w0.102: v1(4.23,46.16) 2.17,46.16 v1(2.12,46.21)
  IN1 w0.102: v1(10.2,43.41) 9.56,43.41 7.66,45.32 7.66,46.13 6.08,47.71 5.22,47.71 4.23,46.72 v1(4.23,46.16)
  BOTTOM w0.102: v1(2.12,46.21) 1.65,46.68 1.65,50.23 3.61,52.19 CR1RTC1.2 ; CN15.2 10.66,43.87 v1(10.2,43.41)
N16894521: length 4.6
  BOTTOM w0.305: FB1WF3.2 C1WF8.2 8.34,5.45 7.32,6.47 U1WF1.8
N16982617: length 2.2
  TOP w0.102: J1USB2.4 5.5,33.35 5.72,33.13 6.15,33.13 R2USB3.2
N16989050: length 3.8
  TOP w0.102: CR1AP1.1 14.53,39.63 R1AP7.1 14.5,39.37 R1AP8.2 15.28,38.11 15.12,37.95 R1AP5.2
N16994583: length 2.8
  TOP w0.102: U1AP1.70 12.55,35.36 13.74,36.55 R1AP1.1
N16996868: length 1.7
  TOP w0.203: U1AP1.5 8.7,32.13 v2(7.88,32.95)
N17078120: length 4.3
  TOP w0.102: U1.AA5 18.74,47.49 v1(18.74,47.49)
  BOTTOM w0.102: v1(18.74,47.49) 18.37,47.86 18.37,49.17 19.01,49.81 19.71,49.81 R60.1
N17101135: length 2.8
  TOP w0.102: v2(25.92,21.57) 25.92,21.06 25.58,20.72 U28.4
  BOTTOM w0.102: v2(25.92,21.57) 25.69,21.8 R62.1
N17133316: length 18.3
  TOP w0.102: U1.U17 16.4,55.13 v1(16.75,55.48)
  IN2 w0.102: v1(16.75,55.48) 16.75,55.91 16.95,56.11 18.35,56.11 18.66,55.8 19.61,55.8 20.03,56.22 20.48,56.22 23.23,58.96 23.23,64.03 25.07,65.87 v2(26.05,65.87)
  BOTTOM w0.102: v2(26.05,65.87) 26.05,65.66 R67.2

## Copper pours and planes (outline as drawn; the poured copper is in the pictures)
+V1P0A on TOP (solid shape): 4.1,56.06 4.18,56.01 4.28,55.99 4.29,55.99 4.39,55.89 4.42,55.89 4.51,55.79 5.46,55.79 5.86,55.39 5.86,55.38 5.92,55.27 6,55.19 6,54.46 5.88,54.33 3.67,54.33 3.52,54.49 3.52,55.91 3.67,56.06
+V1P0A on TOP (solid shape): 5.83,27.69 5.93,27.67 6.02,27.67 6.14,27.55 6.14,25.32 6,25.18 4.78,25.18 4.76,25.18 4.73,25.19 4.73,25.42 4.52,25.63 4.4,25.63 4.36,25.63 4.24,25.63 4.07,25.47 4.07,25.35 4.07,25.26 4.04,25.2 3.98,25.18 3.46,25.18 3.21,25.43 3.21,26.09 2.8,26.5 2.8,26.9 2.86,26.95 3.19,26.95 3.46,27.23 4.46,27.23 4.91,27.69
+V1P0A on TOP (solid shape): 12,49.85 12,49.79 11.97,49.77 11.79,49.49 11.97,49.22 11.98,49.21 12.23,48.97 12.32,48.91 12.43,48.88 12.45,48.89 12.65,48.68 12.65,48.41 12.53,48.29 10.45,48.29 10.43,48.32 10.31,48.47 10.12,48.53 10.06,48.6 10.06,48.62 9.89,48.78 9.85,48.78 9.76,48.87 9.76,48.88 9.72,48.99 9.65,49.08 9.64,49.1 9.64,49.18 9.74,49.28 10.49,49.28 10.6,49.18 10.74,49.13 10.76,49.13 10.86,49.03 10.9,48.97 10.99,48.9 11.1,48.89 11.21,48.9 11.3,48.97 11.37,49.05 11.38,49.13 11.42,49.18 11.42,49.29 11.12,49.59 11.12,49.6 11.06,49.7 10.97,49.79 10.97,49.88 11.14,50.05 11.8,50.05
+V1P0A on BOTTOM (solid shape): 12.71,50.27 12.71,50.07 12.56,49.92 12.25,49.92 12.14,49.8 12.11,49.8 12.06,49.8 11.97,49.79 11.88,49.71 11.8,49.62 11.79,49.5 11.8,49.41 11.8,49.34 11.85,49.3 11.85,48.85 11.84,48.84 11.7,48.84 11.57,48.8 11.5,48.69 11.49,48.65 10.73,48.65 10.58,48.8 10.58,48.85 10.6,48.93 10.66,49 10.71,49.05 10.73,49.12 10.74,49.14 10.79,49.18 10.8,49.18 11.06,49.37 11,49.69 11,49.7 10.98,49.73 11.02,49.81 11.03,49.87 11.08,49.92 11.08,50.32 11.14,50.37 12.61,50.37
+V1P0A on BOTTOM (solid shape): outline of 469 points within 12.46,53.57 23.4,60.94
+V1P0A on GND (solid shape): 17.89,50.37 17.89,49.71 17.79,49.48 17.89,49.25 17.89,47.88 16.29,46.28 13.77,46.28 12.93,47.12 12.86,47.12 12.74,47.15 12.61,47.12 12.22,47.12 12.1,47.15 11.98,47.12 11.4,47.12 11.37,47.1 11.21,47.1 11,47.31 11.02,47.35 10.97,47.72 10.6,47.77 10.56,47.75 10.5,47.81 10.5,48.95 10.64,49.09 10.92,49.09 11.24,49.41 11.24,49.56 11.39,49.71 11.64,49.71 11.8,49.56 11.79,49.54 11.79,49.49 11.8,49.43 11.8,49.26 12.74,48.32 13.04,48.32 13.13,48.23 13.13,48.21 13.13,48.06 13.21,47.93 13.38,47.84 13.57,47.88 13.59,47.88 13.92,47.88 13.93,47.88 14.08,47.83 14.24,47.88 14.25,47.88 15.23,47.88 15.41,47.83 15.58,47.88 16.32,47.88 16.42,47.99 16.42,48.49 16.47,48.58 16.57,48.57 17.04,48.83 16.57,49.09 16.47,49.09 16.42,49.18 16.42,50.22 16.71,50.52 16.73,50.52 16.8,50.52 16.88,50.55 17.71,50.55
+V1P0A on GND (solid shape): outline of 248 points within 4.68,53.98 16.27,56.33
+V1P0A on IN1 (solid shape): 8.67,29.35 8.67,28.9 8.57,28.79 7.99,28.79 7.07,27.88 7.07,26.34 6.82,26.09 5.73,26.09 5.63,26.19 5.63,27.66 5.78,27.81 5.86,27.84 5.93,27.8 6.36,27.77 6.33,28.19 6.28,28.27 6.31,28.35 7.37,29.4 8.62,29.4
+V1P0A on IN2 (solid shape): outline of 1214 points within 3.57,48.72 13.95,57.77
+V1P0A on VCC (solid shape): outline of 1797 points within 2.74,25.61 12.35,49.66
+V1P0A_LX on TOP (solid shape): 8.33,28.63 8.4,28.62 8.46,28.63 9.52,28.63 9.62,28.53 9.52,28.43 8.49,28.43 8.39,28.33 8.14,28.33 7.68,27.87 7.68,25.33 7.48,25.13 6.66,25.13 6.46,25.33 6.46,27.95 6.46,28.07 6.95,28.56 8.07,28.56 8.14,28.63
+V1P0SX on TOP (solid shape): 12.46,40.62 12.46,39.96 12.71,39.71 13.02,39.71 13.24,39.48 13.24,38.31 13.12,38.18 11.19,38.18 11.08,38.28 11.08,40.52 11.34,40.77 12.3,40.77
+V1P0SX on BOTTOM (solid shape): outline of 819 points within 11.07,39.2 18.2,54.34
+V1P0SX on VCC (solid shape): outline of 833 points within 10.58,39.1 17.33,54.39
+V1P0SX_LX on TOP (solid shape): 13.37,37.06 13.37,36.4 12.35,35.39 12.05,35.39 11.24,36.2 11.24,37.14 11.29,37.19 13.24,37.19
+V1P2A on BOTTOM (solid shape): 14.27,48.3 14.31,48.23 14.31,47.74 14.28,47.71 14.28,47.63 13.83,47.17 12.27,47.17 12.25,47.2 11.95,47.2 11.93,47.17 11.59,47.17 11.49,47.27 11.49,47.88 11.64,48.04 13.02,48.04 13.32,48.34 14.23,48.34
+V1P2A on IN2 (solid shape): outline of 561 points within 7.66,27.09 18.81,48.35
+V1P2SX on IN2 (solid shape): outline of 1347 points within 4.09,40.85 15.83,56.65
+V1P8A on TOP (solid shape): 27.33,55.89 27.33,53.4 27.12,53.19 26.41,53.19 26.11,53.5 26.11,54.36 26.26,54.51 26.26,55.68 26.28,55.71 26.28,55.81 26.46,55.99 27.22,55.99
+V1P8A on BOTTOM (solid shape): 18.4,53.6 18.4,53.25 18.24,53.09 18.21,53.09 18.2,53.09 17.79,52.84 18.14,52.51 18.2,52.46 18.2,52.05 17.94,51.8 17.43,51.8 17.18,52.05 17.18,53.08 17.22,53.16 17.31,53.18 17.62,53.26 17.69,53.57 17.7,53.66 17.78,53.7 18.3,53.7
+V1P8A on BOTTOM (solid shape): outline of 533 points within 5.09,35.74 11.08,51.08
+V1P8A on IN1 (solid shape): outline of 753 points within 9.97,46.39 18.37,52.33
+V1P8A on IN2 (solid shape): outline of 1218 points within 23.43,58.53 28.48,86.5
+V1P8A on VCC (solid shape): 11.74,54.28 11.74,53.81 11.69,53.73 11.59,53.73 11.37,53.77 11.18,53.65 11.1,53.61 11.02,53.65 10.55,53.69 10.59,53.22 10.63,53.14 10.59,53.06 10.47,52.77 10.66,52.53 10.66,51.73 10.48,51.51 10.57,51.23 10.57,50.78 10.58,50.78 10.58,50.73 10.42,50.58 10.02,50.58 9.87,50.58 9.66,50.78 9.66,51.05 9.66,51.1 9.63,51.16 9.61,51.21 9.64,51.23 9.73,51.51 9.54,51.74 9.51,51.75 9.51,51.84 9.54,51.85 9.71,52.1 9.55,52.46 9.6,52.54 9.74,52.75 9.66,52.99 9.66,53.24 9.68,53.26 9.75,53.37 9.76,53.5 9.76,53.52 10.73,54.49 11.04,54.49 11.54,54.49
+V1P8A on VCC (solid shape): outline of 924 points within 17.92,49.16 28.72,59.97
+V3P3A on TOP (solid shape): 31.51,90.15 31.51,89.74 31.46,89.69 31.14,89.69 31.05,89.78 31.03,89.77 30.98,89.79 30.97,89.8 30.57,89.88 30.45,89.49 30.46,89.46 30.36,89.36 30.28,89.36 30.13,89.3 30.07,89.16 30.07,89.07 29.42,88.42 29.42,88.27 29.27,88.11 28.59,88.11 28.53,88.17 28.53,88.3 28.55,88.31 28.92,88.31 29.42,88.82 29.42,89.54 29.85,89.97 29.92,90.02 29.97,90.09 30.19,90.3 31.35,90.3
+V3P3A on TOP (solid shape): outline of 123 points within 7.58,17.89 11.11,22.14
+V3P3A on BOTTOM (solid shape): 7.73,25.68 7.73,24.47 7.68,24.41 6.57,24.41 6.46,24.53 6.46,25.74 6.56,25.84 7.58,25.84
+V3P3A on BOTTOM (solid shape): 16.42,4.45 16.42,3.18 16.3,3.06 16.21,3.05 16.13,3.03 13.98,3.03 13.93,3.08 13.93,4.7 13.98,4.75 16.11,4.75
+V3P3A on BOTTOM (solid shape): 9.84,34.4 9.84,33.95 9.76,33.87 9.76,33.45 9.84,33.37 9.84,32.67 9.87,32.64 9.87,32.09 9.76,31.98 9.15,31.98 8.9,32.24 8.9,32.95 8.6,33.25 8.6,33.96 9.21,34.57 9.66,34.57
+V3P3A on BOTTOM (solid shape): 11.95,15.88 11.95,12.7 12.31,12.35 12.39,12.08 12.66,12 14.08,10.57 14.08,7.4 13.93,7.24 13.32,7.24 13.12,7.45 13.12,10.04 11.08,12.07 11.08,15.47 8.54,18.01 8.54,18.27 8.67,18.39 9.43,18.39
+V3P3A on IN1 (solid shape): 12.2,26.44 12.2,25.27 11.77,24.84 11.6,24.84 11.43,25.01 11.43,26.56 11.43,26.59 11.53,26.69 11.95,26.69
+V3P3A on IN1 (solid shape): 10.02,38.84 10.02,35.86 10,35.84 9.97,35.8 9.94,35.76 9.92,35.71 9.92,35.67 9.92,35.62 9.92,35.57 9.94,35.52 9.97,35.48 10,35.44 10.02,35.42 10.02,34.07 9.87,33.91 8.93,33.91 8.7,34.14 8.7,34.88 8.14,35.44 8.14,35.69 9.1,35.69 9.1,35.64 9.11,35.59 9.13,35.54 9.15,35.49 9.18,35.45 9.22,35.41 9.26,35.38 9.31,35.36 9.36,35.34 9.41,35.34 9.46,35.34 9.51,35.34 9.56,35.36 9.61,35.38 9.65,35.41 9.69,35.45 9.72,35.49 9.74,35.54 9.76,35.59 9.76,35.64 9.76,35.69 9.76,35.74 9.74,35.79 9.72,35.84 9.69,35.88 9.65,35.92 9.61,35.95 9.56,35.97 9.51,35.99 9.46,36 9.41,36 9.36,35.99 9.31,35.97 9.26,35.95 9.22,35.92 9.18,35.88 9.15,35.84 9.13,35.79 9.11,35.74 9.1,35.69 8.14,35.69 8.14,35.76 8.15,35.78 8.17,35.82 8.19,35.87 8.19,35.92 8.19,35.97 8.17,36.02 8.15,36.06 8.14,36.08 8.14,38.18 9,39.04 9.81,39.04
+V3P3A on IN1 (solid shape): outline of 94 points within 9.15,49.76 18.2,53.73
+V3P3A on IN2 (solid shape): 15.56,8.82 15.56,3.59 15.3,3.33 14.18,3.33 13.83,3.69 13.83,8.01 13.07,8.77 13.07,9.63 13.37,9.94 14.44,9.94
+V3P3A on IN2 (solid shape): outline of 570 points within 8.04,37.11 11.92,50.33
+V3P3A on VCC (solid shape): outline of 350 points within 5.5,17.93 9.81,34.63
+V3P3A_LX on TOP (solid shape): 11.54,24.62 11.54,23.45 11.24,23.14 9.15,23.14 9.05,23.25 9.05,24.09 9.22,24.26 10.83,24.26 10.88,24.32 10.91,24.31 11.14,24.39 11.24,24.62 11.25,24.65 11.29,24.67 11.49,24.67
+V3P3S_WIFI on BOTTOM (solid shape): 6.31,25.68 6.31,24.52 6.21,24.41 5.34,24.41 5.24,24.52 5.24,25.74 5.32,25.81 6.18,25.81
+V3P3S_WIFI on IN1 (solid shape): outline of 90 points within 5.27,18.45 17.16,25.13
+VDDIO_WIFI on BOTTOM (solid shape): 3.97,27.56 3.97,26.14 3.51,25.68 3.47,25.65 3.44,25.61 3.26,25.43 3.26,24.82 3.16,24.72 1.99,24.72 1.84,24.87 1.84,25.61 2.02,25.79 2.02,26.67 2.14,26.8 2.96,26.8 3.16,27.01 3.16,27.51 3.26,27.61 3.92,27.61
+VDDIO_WIFI on BOTTOM (solid shape): 3.17,22.84 3.41,22.84 3.74,22.52 3.74,19.76 3.62,19.64 1.75,19.64 1.73,19.65 1.68,19.67 1.63,19.69 1.58,19.69 1.53,19.69 1.48,19.67 1.46,19.66 1.38,19.74 1.38,20.3 3.3,20.3 3.3,20.82 2.05,20.82 2.05,20.3 1.38,20.3 1.38,21.48 1.38,21.48 1.38,21.77 1.43,21.8 1.51,21.87 1.59,21.95 1.66,22.03 1.73,22.11 1.79,22.21 1.85,22.3 1.89,22.4 1.93,22.51 1.97,22.61 1.99,22.72 2.01,22.83 2.02,22.94 2.02,23.04 2.97,23.04
+VDDIO_WIFI on IN2 (solid shape): 3.36,25.46 3.36,22.41 3.18,22.23 2.14,22.23 1.84,22.53 1.84,25.53 1.99,25.68 3.14,25.68
+VDDQ on TOP (solid shape): 5.75,29.9 7.99,29.9 8.34,30.26 8.54,30.26 8.57,30.23 9.65,30.23 9.75,30.13 9.65,30.03 8.67,30.03 8.6,29.95 8.6,29.82 8.16,29.39 8.16,29.29 8.11,29.2 8.09,29.09 7.68,28.68 4.99,28.68 4.63,29.04 4.63,30.21 4.84,30.41 5.24,30.41
+VDDQ on TOP (solid shape): 4.68,68.92 4.69,68.9 4.69,67.08 3.88,66.27 3.86,66.26 3.84,66.29 3.84,66.34 3.82,66.42 3.77,66.5 3.68,66.59 3.77,66.68 3.82,66.75 3.84,66.84 3.84,66.97 3.82,67.05 3.77,67.13 3.62,67.28 3.53,67.28 3.51,67.3 3.51,67.33 4.33,68.15 4.33,68.67 4.54,68.88 4.6,68.9 4.65,68.92
+VDDQ on TOP (solid shape): 23.52,76.99 23.55,76.96 23.59,76.93 23.6,76.9 23.57,76.88 23.45,76.88 22.64,76.07 22.31,76.07 21.95,75.71 21.94,75.71 21.72,75.66 21.59,75.47 21.58,75.45 21.55,75.46 20.88,76.13 20.77,76.13 20.75,76.14 20.75,76.17 20.81,76.27 20.82,76.39 20.82,76.4 20.92,76.49 21.65,76.49 21.69,76.49 21.73,76.51 22.18,76.51 22.22,76.49 22.26,76.49 22.4,76.49 22.82,76.41 22.91,76.83 22.91,76.85 22.93,76.86 23.15,76.86 23.25,76.85 23.35,76.9 23.44,76.99
+VDDQ on TOP (solid shape): 7.02,77.2 7.09,77.16 7.12,77.08 7.13,76.91 7.22,76.78 7.24,76.76 7.24,76.75 7.48,76.51 7.61,76.51 7.71,76.45 7.69,76.34 7.06,75.72 7.06,75.7 7.02,75.66 7,75.64 6.91,75.6 6.83,75.65 6.57,75.79 6.31,75.64 6.24,75.59 6.15,75.62 5.75,76.02 5.73,76.13 5.82,76.19 6.42,76.19 6.59,76.36 6.62,76.36 6.94,76.57 6.8,76.93 6.75,77.02 6.8,77.11 6.86,77.15 6.9,77.2
+VDDQ on TOP (solid shape): 13.08,72.63 13.11,72.63 13.12,72.61 13.12,72.43 13.41,72.15 13.65,72.15 13.66,72.14 13.66,70.9 13.12,70.9 12.9,70.67 12.9,70.45 12.91,70.37 12.96,70.29 13.05,70.2 12.96,70.11 12.91,70.04 12.9,69.95 12.9,69.82 12.91,69.74 12.96,69.66 13.05,69.57 13.09,69.54 13.1,69.53 13.09,69.51 13.06,69.48 13.02,69.41 13,69.32 13,69.19 13.02,69.11 13.06,69.03 13.16,68.92 13.09,68.85 13.06,68.81 13.04,68.8 13.02,68.8 12.89,68.84 12.75,68.82 12.72,68.82 12.71,68.84 12.71,70.32 12.38,70.66 12.38,70.84 12.39,70.86 12.41,70.86 12.81,71.02 12.66,71.42 12.64,71.44 12.66,71.47 12.83,71.79 12.56,72.05 12.54,72.06 12.54,72.09
+VDDQ on TOP (solid shape): 21.49,78.62 21.57,78.59 21.59,78.5 21.59,78.43 21.6,78.36 21.58,78.28 21.5,78.24 21.43,78.24 21.41,78.26 21.27,78.26 21.15,78.13 20.77,78.13 20.27,77.96 20.77,77.79 21.29,77.79 21.43,77.93 21.5,77.93 21.58,77.89 21.6,77.8 21.61,77.61 21.74,77.46 21.8,77.37 21.74,77.28 21.61,77.14 21.59,76.96 21.57,76.87 21.49,76.83 20.78,76.83 20.59,76.64 20.52,76.71 20.5,76.82 20.58,76.88 20.74,77.36 20.27,77.2 20.2,77.11 20.1,77.14 20.02,77.21 20.02,77.22 19.94,77.36 19.81,77.44 19.79,77.44 19.72,77.51 19.7,77.62 19.78,77.68 19.96,77.78 20.03,77.97 20.03,78 20.32,78.3 20.32,78.4 20.37,78.48 20.46,78.5 20.63,78.49 20.77,78.59 21.08,78.59 21.11,78.62
+VDDQ on TOP (solid shape): 4.23,74 4.23,73.97 4.19,73.89 4.12,73.87 3.89,73.78 3.8,73.55 3.78,73.48 3.71,73.44 3.43,73.19 3.65,72.89 3.66,72.88 3.78,72.76 3.66,72.64 3.43,72.33 3.72,72.08 3.78,72.04 3.8,71.97 3.8,71.91 3.82,71.85 3.91,71.73 4.05,71.66 4.13,71.59 4.11,71.49 4.09,71.47 4.07,71.46 3.8,71.16 4.07,70.86 4.09,70.86 4.23,70.71 4.23,70.7 4.34,70.54 4.52,70.48 4.67,70.48 4.69,70.46 4.69,70.33 4.65,70.26 4.57,70.23 4.39,70.22 4.26,70.09 4.24,70.05 4.23,70 4,69.77 3.4,69.77 2.71,69.08 2.71,66.85 2.65,66.76 2.54,66.78 1.38,67.94 1.38,67.95 1.18,68.15 1.18,69.12 1.23,69.17 1.69,69.17 1.79,69.27 1.79,69.98 2.09,70.27 2.1,70.28 2.37,70.58 2.1,70.88 2.09,70.88 1.86,71.11 1.86,72.4 3.06,73.59 3.05,73.59 3.21,73.72 3.25,73.91 3.24,73.94 3.5,74.19 4.03,74.19
+VDDQ on TOP (solid shape): 7.01,81.01 7.11,81.01 7.14,81 7.2,80.98 7.2,80.79 7.11,80.54 7.27,80.31 7.32,80.22 7.11,79.86 7.32,79.51 7.11,79.15 7.32,78.8 7.27,78.71 7.12,78.54 7.14,78.31 7.14,78.3 7.14,78.24 7.09,78.24 7.07,78.23 6.99,78.2 6.91,78.24 6.79,78.36 6.62,78.39 6.59,78.38 6.47,78.51 5.89,78.51 5.79,78.57 5.82,78.68 6.12,78.99 6.34,78.99 6.48,78.85 6.48,78.83 6.99,78.58 6.75,79.1 6.72,79.1 6.66,79.16 6.7,79.21 6.72,79.21 6.95,79.46 6.8,79.77 6.75,79.86 6.8,79.95 6.96,80.26 6.73,80.51 6.71,80.52 6.67,80.56 6.74,80.64 6.75,80.64 6.9,80.75 6.96,80.93
+VDDQ on TOP (solid shape): outline of 216 points within 14.61,77.09 17.13,82.29
+VDDQ on TOP (solid shape): outline of 88 points within 4.87,66.14 7.56,73.35
+VDDQ on TOP (solid shape): outline of 294 points within 8.71,65.94 11.02,72.91
+VDDQ on TOP (solid shape): outline of 347 points within 24.01,73.44 28.75,76.86
+VDDQ on TOP (solid shape): outline of 403 points within 23.87,63.35 28.75,73.14
+VDDQ on TOP (solid shape): outline of 3557 points within 1.18,66.27 27.76,86.44
+VDDQ on BOTTOM (solid shape): 23.6,81.43 23.6,80.6 23.47,80.43 23.5,80.22 23.51,80.21 23.51,80.15 23.41,80.15 23.3,80.26 23.3,80.8 22.99,81.1 22.91,81.1 22.86,81.15 22.8,81.2 22.75,81.28 22.8,81.37 22.93,81.5 22.96,81.67 22.95,81.7 23.01,81.75 23.28,81.75
+VDDQ on BOTTOM (solid shape): 5.9,76.85 6.28,76.85 6.32,76.85 6.37,76.86 6.4,76.85 6.39,76.83 6.49,76.4 6.92,76.51 7.68,76.51 7.72,76.49 7.76,76.49 8.13,76.49 8.23,76.4 8.23,76.39 8.24,76.28 8.29,76.19 8.29,76.16 8.27,76.15 8.07,76.15 7.53,75.61 7.53,75.57 7.51,75.57 7.51,75.58 7.38,75.72 7.19,75.75 7.18,75.75 6.88,76.05 6.58,76.05 5.72,76.91 5.51,76.91 5.48,76.92 5.49,76.95 5.53,76.99 5.76,76.99
+VDDQ on BOTTOM (solid shape): outline of 82 points within 21.43,71.27 24.27,74.11
+VDDQ on BOTTOM (solid shape): outline of 104 points within 2.14,73.44 5.05,77.35
+VDDQ on BOTTOM (solid shape): outline of 987 points within 1.13,75.77 13.38,84.05
+VDDQ on BOTTOM (solid shape): outline of 7520 points within 1.11,28.94 29.44,84.05
+VDDQ on GND (solid shape): 13.74,58.65 13.83,58.61 14.07,58.48 14.41,58.64 14.49,58.59 14.52,58.55 14.56,58.52 14.6,58.44 14.57,58.36 14.45,58.12 14.6,57.81 14.56,57.73 14.74,57.18 14.94,57.72 14.9,57.8 14.94,57.88 15.06,58.12 14.94,58.37 14.89,58.45 14.93,58.53 14.96,58.56 14.99,58.59 15.07,58.63 15.16,58.59 15.37,58.47 15.61,58.55 15.64,58.58 15.86,58.36 15.83,58.33 15.75,58.09 15.89,57.87 15.89,57.73 15.75,57.47 15.89,57.22 15.89,57.02 15.78,56.87 15.79,56.68 15.8,56.65 15.55,56.4 15.52,56.41 15.37,56.43 15.23,56.37 14.93,56.37 14.75,56.43 14.56,56.37 14.27,56.37 14.25,56.38 14.2,56.47 14.25,56.56 14.32,57.04 13.84,56.98 13.75,56.93 13.66,56.98 13.63,57.03 13.59,57.07 13.55,57.15 13.71,57.47 13.55,57.8 13.71,58.12 13.55,58.45 13.59,58.53 13.63,58.57 13.66,58.61
+VDDQ on GND (solid shape): outline of 4693 points within 3.01,55.92 25.46,85.46
+VDDQ on IN2 (solid shape): outline of 917 points within 1.81,28.89 6.85,82.05
+VDDQ on VCC (solid shape): 27.12,63.76 27.12,63.1 27.07,63.01 26.97,63.01 26.57,62.92 26.61,62.51 26.65,62.44 26.61,62.36 26.51,62.14 26.6,61.92 26.62,61.88 26.51,61.6 26.64,61.38 26.68,61.32 26.67,61.26 26.7,61.23 26.68,61.18 26.67,61.17 26.59,61.06 26.56,60.92 26.76,60.66 27.08,60.72 27.12,60.74 27.17,60.74 27.22,60.72 27.29,60.64 27.29,60.63 27.38,60.47 27.54,60.39 27.55,60.38 27.58,60.36 27.58,59.8 27.22,59.44 27.1,59.44 27.01,59.48 27,59.58 26.78,60.03 26.33,59.81 26.25,59.74 26.16,59.77 25.85,60.08 25.26,60.08 25.03,59.85 25.03,58.59 25.65,57.97 25.65,57.91 25.63,57.87 25.58,57.86 25.56,57.87 25.15,57.8 25.19,57.38 25.22,57.27 25.13,57.21 24.28,57.21 24.14,57.34 24.14,60.74 24.54,61.14 25.61,62.2 25.61,62.97 25.65,63.06 25.74,63.07 26.14,63.25 25.95,63.64 25.88,63.72 25.91,63.81 26.06,63.96 26.92,63.96
+VDDQ on VCC (solid shape): outline of 4132 points within 3.89,70.95 25.21,86
+VDDQ_LX on TOP (solid shape): 7.62,31.52 7.84,31.52 8,31.36 8,31.13 8.5,30.63 9.65,30.63 9.75,30.53 9.65,30.43 6.11,30.43 5.9,30.63 5.9,31.48 5.95,31.53 7.62,31.53
GND on TOP (solid shape): 12.71,42.09 12.71,41.64 12.46,41.38 11.24,41.38 11.08,41.53 11.08,41.94 11.29,42.14 12.66,42.14
GND on TOP (solid shape): 17.79,38.73 17.79,36.09 17.7,36 16.8,36 16.61,36.19 16.61,37.45 16.54,37.52 16.54,38.93 16.67,39.06 17.47,39.06
GND on TOP (solid shape): 28.54,59.54 29.56,59.54 29.76,59.34 29.76,58.88 29.61,58.73 27.78,58.73 27.73,58.78 27.73,59.85 27.83,59.95 28.14,59.95
GND on TOP (solid shape): 24.01,37.07 24.01,33.59 22.31,31.88 20.98,31.88 20.66,32.2 20.66,33.77 20.77,33.87 21.83,33.87 22.19,34.23 22.19,36.97 22.44,37.23 23.86,37.23
GND on TOP (solid shape): 4.1,69.28 4.1,69.07 3.89,68.86 3.89,68.33 3.27,67.71 3.2,67.64 3.17,67.64 3.15,67.66 3.15,68.9 3.58,69.33 4.05,69.33
GND on TOP (solid shape): 18.99,83.3 18.99,82.95 18.58,82.54 18.58,82.29 18.38,82.08 18.19,82.08 18.13,82.13 18.13,82.48 18.16,82.55 18.23,82.58 18.23,83.2 18.38,83.35 18.94,83.35
GND on TOP (solid shape): 6.03,41.14 6.03,40.99 6.15,40.87 6.67,40.87 6.8,40.74 6.8,40.44 6.64,40.28 6.15,40.28 6.11,40.33 6.08,40.33 6.03,40.38 5.47,40.38 5.37,40.27 4.97,40.27 4.87,40.37 4.87,40.93 4.93,40.99 4.97,40.98 5.27,40.98 5.42,40.99 5.68,41.24 5.93,41.24
GND on TOP (solid shape): 21.91,28.43 21.91,27.56 21.4,27.06 21.4,25.21 21.4,24.87 21.84,24.43 22.83,24.43 23,24.26 26.92,24.26 27.01,24.18 27.01,23.87 27.2,23.68 27.39,23.68 27.52,23.55 27.52,23.38 26.93,22.79 25.87,22.79 25.61,22.53 23.99,22.53 23.63,22.89 22.16,22.89 21.55,22.28 21.19,22.28 21.09,22.38 21.09,23.22 20.78,23.54 20.78,24.72 20.84,24.78 20.84,28.36 20.97,28.49 21.84,28.49
GND on TOP (solid shape): 19.89,73.39 19.91,73.38 19.91,73.36 19.9,73.29 19.91,73.22 19.9,73.07 19.77,72.98 19.72,72.98 19.59,72.84 19.59,72.75 19.06,72.22 18.82,72.22 18.82,72.23 18.75,72.32 18.69,72.34 18.68,72.36 18.66,72.53 18.55,72.66 18.55,73.13 18.81,73.39
GND on TOP (solid shape): 25.51,32.34 25.51,30 25.66,29.85 26.17,29.85 26.32,29.7 26.32,29.04 27.19,29.04 27.44,28.78 27.44,27.94 26.88,27.38 26.88,25.18 26.86,25.15 24.73,25.15 24.58,25.3 24.58,26.14 25.71,26.14 25.72,26.09 25.73,26.04 25.75,25.99 25.78,25.94 25.81,25.9 25.85,25.86 25.89,25.83 25.94,25.81 25.99,25.79 26.04,25.79 26.1,25.79 26.15,25.79 26.2,25.81 26.25,25.83 26.29,25.86 26.33,25.9 26.37,25.94 26.39,25.99 26.41,26.04 26.42,26.09 26.43,26.14 26.42,26.19 26.41,26.25 26.39,26.3 26.37,26.34 26.33,26.38 26.29,26.42 26.25,26.45 26.2,26.47 26.15,26.49 26.1,26.5 26.04,26.5 25.99,26.49 25.94,26.47 25.89,26.45 25.85,26.42 25.81,26.38 25.78,26.34 25.75,26.3 25.73,26.25 25.72,26.19 25.71,26.14 24.58,26.14 24.58,28.4 24.13,28.86 24.13,32.12 24.39,32.39 25.46,32.39
GND on TOP (solid shape): 19.8,73.39 19.87,73.36 19.9,73.29 19.9,73.26 19.92,73.17 19.92,73.11 19.91,73.08 19.86,73.02 19.79,72.99 19.75,72.98 19.6,72.81 19.6,72.7 19.61,72.66 19.61,72.62 19.59,72.59 19.56,72.57 19.54,72.55 19.52,72.54 19.5,72.53 19.46,72.53 19.07,72.13 18.87,72.13 18.83,72.15 18.81,72.18 18.8,72.27 18.71,72.33 18.69,72.35 18.68,72.38 18.66,72.53 18.56,72.66 18.55,72.69 18.55,73.13 18.81,73.39
GND on TOP (solid shape): 10.85,35.02 10.95,35.12 11.05,35.02 11.05,33.84 11.05,33.77 11.05,33.71 11.05,33 16.57,33 16.57,32.49 16.93,32.14 16.93,26.5 16.77,26.34 16.16,26.34 16.06,26.45 16.06,26.62 15.61,27.08 10.65,27.08 10.11,27.63 8.86,27.63 8.76,27.73 8.86,27.83 10.55,27.83 10.66,27.93 10.66,31.28 10.58,31.36 10.58,32.01 10.67,32.31 10.44,32.54 10.4,32.54 10.4,33.63 10.85,34.08
GND on TOP (solid shape): 17.57,53.64 17.63,53.6 17.7,53.58 17.77,53.54 17.79,53.47 17.78,53.41 17.74,53.4 17.73,53.4 17.49,53.24 17.55,52.96 17.66,52.85 17.69,52.76 17.63,52.69 17.57,52.64 17.52,52.58 17.43,52.49 17.37,52.48 17.34,52.52 17.34,52.69 17.07,52.96 16.99,52.96 16.89,53.07 16.89,53.15 16.86,53.18 16.86,53.49 16.9,53.57 16.99,53.59 17.12,53.58 17.23,53.64 17.26,53.68 17.53,53.68
GND on TOP (solid shape): 14.03,40.42 14.03,39.3 14.41,38.92 14.74,38.92 14.82,38.83 14.82,38.29 14.54,38.02 14.52,38.02 14.42,37.94 14.37,37.87 14.17,37.67 13.96,37.67 13.81,37.61 13.76,37.47 13.76,37.36 13.31,37.36 13.24,37.29 11.17,37.29 11.16,37.28 11.07,37.26 11,37.31 10.7,37.47 10.44,37.25 10.43,37.22 8.44,37.22 8.29,37.06 6.39,37.06 6.3,37.15 6.3,37.99 6.67,38.37 6.7,38.36 7.02,38.46 7.12,38.78 7.11,38.81 7.25,38.94 8.65,38.94 9.06,38.53 9.06,38.52 9.39,38.21 9.8,38.38 10.73,38.38 11.03,38.08 12.76,38.08 13.16,38.08 13.35,38.27 13.35,39.52 13.06,39.81 12.84,39.81 12.76,39.88 12.76,40.58 12.86,40.65 12.89,40.67 13.78,40.67
GND on TOP (solid shape): 24.25,78.01 24.26,77.99 24.27,77.97 24.44,77.7 24.76,77.78 24.79,77.8 24.83,77.79 24.88,77.77 24.94,77.76 25.08,77.72 25.15,77.59 25.16,77.53 25.34,77.35 25.39,77.34 25.5,77.25 25.51,77.1 25.5,77.07 25.5,77.02 25.49,76.98 25.45,76.97 25.2,76.97 25.18,76.97 25.06,77.05 24.93,77.07 24.86,77.09 24.83,77.17 24.68,77.41 24.34,77.39 24.31,77.44 24.31,77.44 24.03,77.72 24.02,77.72 23.97,77.75 23.98,77.8 24.03,77.97 23.97,78.13 23.96,78.19 24.01,78.22 24.05,78.22
GND on TOP (solid shape): 24.59,72.07 24.64,72.03 24.64,72.01 24.64,71.99 24.82,71.68 25.18,71.76 25.21,71.78 25.24,71.77 25.29,71.75 25.35,71.74 25.52,71.58 25.39,71.39 25.34,71.38 25.13,71.16 25.34,70.95 25.39,70.94 25.47,70.64 25.17,70.72 25.16,70.76 24.98,70.95 24.92,70.96 24.8,71.02 24.74,71.14 24.74,71.19 24.69,71.24 24.59,71.29 24.48,71.28 24.46,71.28 24.41,71.31 24.29,71.43 24.11,71.46 24.1,71.46 24.08,71.47 24.03,71.52 24.03,71.56 24.06,71.63 24.13,71.66 24.36,71.75 24.45,71.98 24.48,72.05 24.55,72.08
